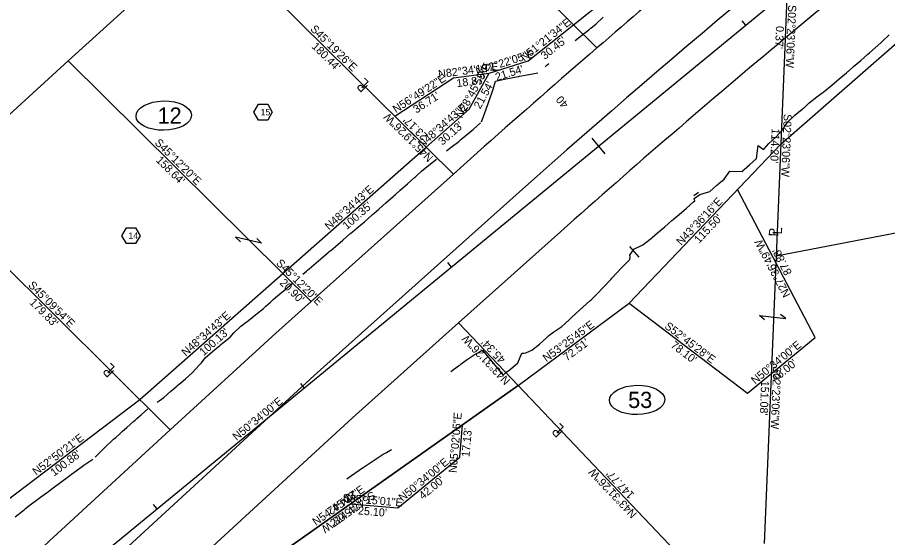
# Model space of a CAD drawing. Extents: x 1145508 to 2262867, y -3126236 to 2021677.
# Drawn here: x 1147204 to 1147660.6, y 2017213 to 2017486.3 of the extents above; entities that cross this region are included whole.
import ezdxf

# ---------------------------------------------------------------- set-up
doc = ezdxf.new("R2010")
doc.units = 0
for name, color, linetype in [('Default', 7, 'Continuous'), ('DSN_DRFT_Guideline-No-Plot', 7, 'Continuous'), ('DSN_RDWY_Alignment Annotation', 7, 'Continuous'), ('DSN_RDWY_Const Limits', 7, 'Continuous'), ('DSN_ROW_Annotation', 7, 'Continuous'), ('DSN_ROW_Esmnt', 7, 'Continuous'), ('DSN_ROW_Line', 7, 'Continuous'), ('DSN_ROW_Line-Annotation', 7, 'Continuous'), ('DSN_ROW_Prop-Line', 7, 'Continuous'), ('DSN_ROW_Prop-Line-Annotation', 7, 'Continuous'), ('E_Const Align', 7, 'Continuous'), ('EX_QSECTION', 7, 'Continuous'), ('EX_ROW', 7, 'Continuous'), ('EX_ROW_ANNOT', 7, 'Continuous'), ('EX_SIGN', 7, 'Continuous'), ('EX_SUBDIV_ANNOT', 7, 'Continuous')]:
    doc.layers.add(name, color=color, linetype=linetype)

msp = doc.modelspace()

# ---------------------------------------------------------------- linework, layer by layer
at = {"layer": 'Default'}
for p, q in [((1147468.99, 2017396.01), (1147359.68, 2017298.15)), ((1147359.68, 2017298.15), (1147243.01, 2017190.89))]:
    msp.add_line(p, q, dxfattribs=at)
msp.add_arc((1150521.47, 2013976.61), 4583.66, 127.59365, 131.75523, dxfattribs=at)
at = {"layer": 'DSN_DRFT_Guideline-No-Plot'}
msp.add_line((1147448.99, 2017418.38), (1147432.84, 2017403.92), dxfattribs=at)
msp.add_line((1147448.99, 2017418.38), (1147432.84, 2017403.92), dxfattribs=at)
msp.add_line((1147448.99, 2017418.38), (1147432.84, 2017403.92), dxfattribs=at)
at = {"layer": 'DSN_RDWY_Alignment Annotation'}
for p, q in [((1147584.16, 2017484.48), (1147586.06, 2017482.16)), ((1147505.44, 2017422.77), (1147512.18, 2017414.57)), ((1147429.69, 2017357.44), (1147431.59, 2017355.13)), ((1147352.45, 2017293.93), (1147354.36, 2017291.61)), ((1147275.21, 2017230.41), (1147277.12, 2017228.09))]:
    msp.add_line(p, q, dxfattribs=at)
at = {"layer": 'DSN_RDWY_Const Limits'}
for points in [[(1147496.71, 2017474.1), (1147499.91, 2017476.72), (1147503.82, 2017479.83), (1147504.53, 2017480.4), (1147504.86, 2017480.66), (1147507.73, 2017482.95), (1147511.41, 2017486.35)], [(1147431.44, 2017300.2), (1147435.5, 2017303.15), (1147436.06, 2017303.57), (1147436.9, 2017304.19), (1147439.51, 2017306.13), (1147443.66, 2017308.94), (1147443.67, 2017308.95), (1147448.08, 2017311.45), (1147458.78, 2017298.45), (1147459.37, 2017298.88), (1147460.12, 2017299.47), (1147462.73, 2017301.51), (1147466.58, 2017304.71), (1147468.77, 2017309.92), (1147469.66, 2017309.96), (1147470.86, 2017310.01), (1147473.95, 2017311.49), (1147477.88, 2017314.59), (1147481.56, 2017317.98), (1147482.08, 2017318.47), (1147482.77, 2017319.1), (1147485.55, 2017321), (1147489.69, 2017323.84), (1147493.34, 2017327.27), (1147493.86, 2017327.74), (1147494.55, 2017328.38), (1147497.03, 2017330.66), (1147500.71, 2017334.05), (1147504.4, 2017337.43), (1147505, 2017337.97), (1147505.51, 2017338.47), (1147507.98, 2017340.95), (1147511.53, 2017344.51), (1147514.98, 2017348.19), (1147515.52, 2017348.78), (1147516, 2017349.31), (1147518.39, 2017351.91), (1147521.12, 2017354.89), (1147521.81, 2017355.63), (1147525.41, 2017359.13), (1147525.56, 2017360.29), (1147525.45, 2017361.3), (1147527.51, 2017364.44), (1147532.11, 2017366.72), (1147536.05, 2017369.8), (1147536.7, 2017370.35), (1147537.12, 2017370.72), (1147539.85, 2017373.05), (1147543.65, 2017376.3), (1147547.45, 2017379.55), (1147548.09, 2017380.09), (1147548.53, 2017380.47), (1147551.26, 2017382.8), (1147555.06, 2017386.04), (1147558.81, 2017389.35), (1147559.5, 2017389.94), (1147559.07, 2017391.13), (1147562.04, 2017393.3), (1147567.32, 2017394.75), (1147571.07, 2017398.06), (1147571.75, 2017398.66), (1147572.07, 2017398.94), (1147574.83, 2017401.37), (1147577.87, 2017405.54), (1147584.45, 2017405.4), (1147585.09, 2017406.05), (1147585.38, 2017406.37), (1147588.08, 2017408.86), (1147591.78, 2017412.23), (1147592.73, 2017418.96), (1147595.55, 2017416.94), (1147595.82, 2017417.28), (1147598.34, 2017420.01), (1147602.05, 2017423.37), (1147605.4, 2017427.16), (1147605.97, 2017427.98), (1147606.14, 2017428.24), (1147608.36, 2017431.44), (1147611.91, 2017434.99), (1147615.87, 2017438.04), (1147616.7, 2017438.7), (1147616.77, 2017438.76), (1147619.52, 2017441.48), (1147623.43, 2017444.6), (1147627.49, 2017447.53), (1147628.34, 2017448.16), (1147628.42, 2017448.21), (1147631.44, 2017450.6), (1147635.19, 2017453.92), (1147638.99, 2017457.16), (1147639.8, 2017457.85), (1147639.87, 2017457.9), (1147642.8, 2017460.41), (1147646.54, 2017463.72), (1147650.35, 2017466.97), (1147651.15, 2017467.65), (1147651.22, 2017467.71), (1147654.15, 2017470.22), (1147657.11, 2017472.91), (1147657.85, 2017473.59), (1147661.49, 2017477.04)], [(1147480.98, 2017460.38), (1147481.61, 2017460.93), (1147482.04, 2017461.31), (1147482.8, 2017461.98)], [(1147447.52, 2017431.47), (1147447.8, 2017432.24), (1147449.19, 2017436.06), (1147450.76, 2017440.44), (1147451.15, 2017441.54), (1147453.11, 2017447.04), (1147453.44, 2017447.98), (1147453.66, 2017448.6), (1147454.86, 2017452.78), (1147460.34, 2017453.99), (1147465.9, 2017455.09), (1147466.86, 2017455.27), (1147467.48, 2017455.39), (1147471.5, 2017456.16), (1147477.09, 2017457.24)], [(1147429.22, 2017416.09), (1147431.65, 2017418.03), (1147435.59, 2017421.11), (1147436.18, 2017421.65), (1147436.72, 2017422.12), (1147439.42, 2017424.32), (1147443.29, 2017427.49), (1147447, 2017430.85)], [(1147353.83, 2017351.44), (1147355.65, 2017353), (1147356.21, 2017353.48), (1147357, 2017354.16), (1147359.45, 2017356.26), (1147363.24, 2017359.52), (1147367.07, 2017362.74), (1147367.61, 2017363.2), (1147368.42, 2017363.87), (1147370.89, 2017365.96), (1147374.68, 2017369.23), (1147378.46, 2017372.5), (1147379, 2017372.96), (1147379.79, 2017373.63), (1147382.28, 2017375.73), (1147386.09, 2017378.95), (1147386.09, 2017378.96), (1147389.83, 2017382.28), (1147389.84, 2017382.28), (1147390.39, 2017382.76), (1147391.11, 2017383.39), (1147393.6, 2017385.58), (1147397.35, 2017388.89), (1147401.1, 2017392.2), (1147401.64, 2017392.68), (1147402.35, 2017393.31), (1147404.86, 2017395.5), (1147408.62, 2017398.8), (1147412.36, 2017402.12), (1147412.9, 2017402.6), (1147413.59, 2017403.22), (1147416.1, 2017405.45), (1147419.91, 2017408.69), (1147423.83, 2017411.8)], [(1147277.32, 2017284.18), (1147278.34, 2017284.91), (1147280.75, 2017286.65), (1147284.51, 2017289.94), (1147287.58, 2017292.51), (1147288.34, 2017293.16), (1147288.92, 2017293.65), (1147289.88, 2017294.46), (1147292.21, 2017296.33), (1147295.89, 2017299.72), (1147299.27, 2017303.49), (1147299.81, 2017304.06), (1147300.64, 2017304.88), (1147302.56, 2017307.35), (1147306.28, 2017310.71), (1147310.16, 2017313.86), (1147310.75, 2017314.34), (1147311.65, 2017315.07), (1147314.04, 2017317.01), (1147315.54, 2017318.34), (1147317.57, 2017320.59), (1147321.25, 2017323.99), (1147321.94, 2017324.52), (1147322.64, 2017325.08), (1147325.18, 2017327.08), (1147329.11, 2017330.18), (1147333.02, 2017333.29), (1147333.54, 2017333.77), (1147334.41, 2017334.57), (1147336.72, 2017336.67), (1147338.22, 2017337.99), (1147340.51, 2017339.93), (1147344.32, 2017343.17), (1147344.84, 2017343.62), (1147345.74, 2017344.39), (1147348.12, 2017346.42)], [(1147244.69, 2017255.31), (1147246.67, 2017257.24), (1147250.27, 2017260.74), (1147253.93, 2017264.16), (1147254.45, 2017264.63), (1147255.58, 2017265.65), (1147257.64, 2017267.52), (1147259.13, 2017268.86), (1147261.35, 2017270.88), (1147265.13, 2017274.15), (1147265.73, 2017274.69), (1147266.66, 2017275.54), (1147268.84, 2017277.51), (1147272.34, 2017280.62)], [(1147376.83, 2017243.81), (1147379.22, 2017245.63), (1147383.38, 2017248.44), (1147384.1, 2017248.93), (1147384.84, 2017249.43), (1147387.54, 2017251.25), (1147391.71, 2017254.05), (1147395.96, 2017256.76), (1147396.58, 2017257.12), (1147397.62, 2017257.71), (1147400.31, 2017259.34)], [(1147202.85, 2017223.93), (1147206.77, 2017227.04), (1147207.7, 2017227.79), (1147208.24, 2017228.23), (1147210.71, 2017230.12), (1147214.72, 2017233.12), (1147218.73, 2017236.1), (1147218.74, 2017236.11), (1147219.52, 2017236.69), (1147220.4, 2017237.35), (1147222.74, 2017239.09), (1147222.75, 2017239.1), (1147226.75, 2017242.1), (1147230.76, 2017245.1), (1147231.52, 2017245.67), (1147232.41, 2017246.34), (1147234.76, 2017248.11), (1147238.87, 2017250.98), (1147242.99, 2017253.84), (1147243.59, 2017254.25)]]:
    msp.add_lwpolyline(points, dxfattribs=at)
at = {"layer": 'DSN_ROW_Esmnt'}
for p, q in [((1147432.75, 2017454.48), (1147451.46, 2017456.92)), ((1147432.75, 2017454.48), (1147451.46, 2017456.92)), ((1147402.03, 2017434.39), (1147432.75, 2017454.48)), ((1147402.03, 2017434.39), (1147432.75, 2017454.48)), ((1147421.07, 2017415.56), (1147402.03, 2017434.39)), ((1147418.5, 2017418.1), (1147402.03, 2017434.39)), ((1147432.84, 2017403.92), (1147432.84, 2017403.92)), ((1147622.64, 2017318.03), (1147581.91, 2017395.9)), ((1147524.94, 2017336.08), (1147587.11, 2017288.82)), ((1147587.11, 2017288.82), (1147622.64, 2017318.03)), ((1147436.06, 2017255.23), (1147437.57, 2017272.29)), ((1147403.62, 2017228.55), (1147436.06, 2017255.23)), ((1147378.61, 2017230.63), (1147403.62, 2017228.55))]:
    msp.add_line(p, q, dxfattribs=at)
at = {"layer": 'DSN_ROW_Line'}
for p, q in [((1147604.59, 2017419.72), (1147751.67, 2017548.43)), ((1147495.77, 2017482.46), (1147559.99, 2017533.8)), ((1147471.99, 2017463.44), (1147495.77, 2017482.46)), ((1147451.46, 2017456.92), (1147471.99, 2017463.44)), ((1147441.09, 2017438.03), (1147451.46, 2017456.92)), ((1147418.5, 2017418.1), (1147441.09, 2017438.03)), ((1147524.94, 2017336.08), (1147604.59, 2017419.72)), ((1147343.25, 2017351.71), (1147418.5, 2017418.1)), ((1147268.17, 2017285.46), (1147343.25, 2017351.71)), ((1147466.71, 2017292.88), (1147524.94, 2017336.08)), ((1147466.71, 2017292.88), (1147283.43, 2017163.37)), ((1147283.43, 2017163.37), (1147466.71, 2017292.88)), ((1147187.77, 2017224.53), (1147268.17, 2017285.46))]:
    msp.add_line(p, q, dxfattribs=at)
at = {"layer": 'DSN_ROW_Line-Annotation'}
for centre in [(1147280.76, 2017434.67), (1147529.2, 2017285.28)]:
    msp.add_ellipse(centre, major_axis=(14.54, 0.23), ratio=0.529773, dxfattribs=at)
at = {"layer": 'DSN_ROW_Prop-Line'}
for p, q in [((1147379.86, 2017596.84), (1147508.13, 2017470.27)), ((1147230.67, 2017463.48), (1147304.54, 2017530.78)), ((1147304.54, 2017530.78), (1147432.84, 2017403.92)), ((1147156.81, 2017396.18), (1147230.67, 2017463.48)), ((1147230.67, 2017463.48), (1147343.25, 2017351.71)), ((1148025.23, 2017442.03), (1147602.14, 2017360.88)), ((1147156.81, 2017396.18), (1147284.33, 2017269.39)), ((1147343.25, 2017351.71), (1147358.08, 2017336.99)), ((1147466.71, 2017292.88), (1147435.49, 2017325.75)), ((1147568.47, 2017185.74), (1147466.71, 2017292.88))]:
    msp.add_line(p, q, dxfattribs=at)
at = {"layer": 'DSN_ROW_Prop-Line-Annotation'}
for p, q in [((1147332.04, 2017367.63), (1147318.44, 2017370.79)), ((1147318.44, 2017370.79), (1147320.95, 2017368.28)), ((1147329.54, 2017370.13), (1147332.04, 2017367.63)), ((1147596.12, 2017327.42), (1147593.35, 2017329.63)), ((1147593.35, 2017329.63), (1147607.22, 2017328.02)), ((1147607.22, 2017328.02), (1147604.45, 2017330.23))]:
    msp.add_line(p, q, dxfattribs=at)
at = {"layer": 'E_Const Align'}
msp.add_line((1146840, 2016868.61), (1147825.51, 2017679.08), dxfattribs=at)
at = {"layer": 'EX_QSECTION'}
for p, q in [((1147610.26, 2017555.82), (1147606.91, 2017475.35)), ((1147606.9, 2017474.98), (1147602.14, 2017360.88)), ((1147606.91, 2017475.35), (1147606.9, 2017474.98)), ((1147602.14, 2017360.88), (1147595.86, 2017209.92))]:
    msp.add_line(p, q, dxfattribs=at)
at = {"layer": 'EX_ROW'}
for p, q in [((1147432.84, 2017403.92), (1147448.99, 2017418.38)), ((1147358.08, 2017336.99), (1147432.84, 2017403.92)), ((1147435.49, 2017325.75), (1147488.96, 2017373.63)), ((1147339.52, 2017320.37), (1147358.08, 2017336.99)), ((1147379.84, 2017275.93), (1147435.49, 2017325.75)), ((1147284.21, 2017269.51), (1147339.52, 2017320.37)), ((1147270.92, 2017175.79), (1147379.84, 2017275.93)), ((1147222.71, 2017212.97), (1147284.21, 2017269.51))]:
    msp.add_line(p, q, dxfattribs=at)
for centre, radius, start, end in [((1150521.47, 2013976.61), 4553.66, 127.59365, 129.79541), ((1150521.47, 2013976.61), 4613.66, 129.9481, 130.77845), ((1150521.47, 2013976.61), 4553.66, 129.79541, 131.75523), ((1150521.47, 2013976.61), 4613.66, 130.77845, 131.75549), ((1145304.01, 2019299.75), 2834.79, 312.2638, 312.59711)]:
    msp.add_arc(centre, radius, start, end, dxfattribs=at)
at = {"layer": 'EX_SIGN'}
for p, q in [((1147558.98, 2017392.72), (1147561.35, 2017394.53)), ((1147525.24, 2017365.86), (1147530.15, 2017360.31))]:
    msp.add_line(p, q, dxfattribs=at)
at = {"layer": 'EX_SUBDIV_ANNOT'}
for p, q in [((1147328.1, 2017436.5), (1147330.5, 2017440.66)), ((1147330.5, 2017440.66), (1147335.3, 2017440.66)), ((1147335.3, 2017440.66), (1147337.7, 2017436.5)), ((1147330.5, 2017432.34), (1147328.1, 2017436.5)), ((1147335.3, 2017432.34), (1147330.5, 2017432.34)), ((1147337.7, 2017436.5), (1147335.3, 2017432.34)), ((1147258.74, 2017371.58), (1147261.14, 2017375.74)), ((1147261.14, 2017375.74), (1147265.94, 2017375.74)), ((1147265.94, 2017375.74), (1147268.34, 2017371.58)), ((1147261.14, 2017367.42), (1147258.74, 2017371.58)), ((1147268.34, 2017371.58), (1147265.95, 2017367.42)), ((1147265.95, 2017367.42), (1147261.14, 2017367.42))]:
    msp.add_line(p, q, dxfattribs=at)

# ---------------------------------------------------------------- texts
at = {"layer": 'DSN_DRFT_Guideline-No-Plot'}
for rotation, p in [(357.0104, (1147495.72, 2017482.41)), (357.0104, (1147495.72, 2017482.41)), (357.0104, (1147495.72, 2017482.41)), (357.0104, (1147495.72, 2017482.41)), (357.0104, (1147495.73, 2017482.41)), (304.3313, (1147451.39, 2017456.93)), (304.3313, (1147451.39, 2017456.93)), (39.4333, (1147451.45, 2017456.85)), (39.4333, (1147451.45, 2017456.85)), (39.4333, (1147451.45, 2017456.85)), (39.4333, (1147451.45, 2017456.85)), (20.3026, (1147432.72, 2017454.41)), (20.3026, (1147432.72, 2017454.41)), (29.2871, (1147432.74, 2017454.42)), (178.3726, (1147418.54, 2017418.15)), (178.3726, (1147418.55, 2017418.15)), (178.3726, (1147418.55, 2017418.15)), (178.5801, (1147432.88, 2017403.97)), (178.5801, (1147432.89, 2017403.97)), (178.5801, (1147432.89, 2017403.97)), (178.5801, (1147432.89, 2017403.97)), (178.5801, (1147432.89, 2017403.97)), (352.0045, (1147581.87, 2017395.86)), (258.5235, (1147622.6, 2017318.08)), (181.0956, (1147587.15, 2017288.87))]:
    msp.add_text('+', height=0.1, rotation=rotation, dxfattribs=at).set_placement(p)
at = {"layer": 'DSN_RDWY_Alignment Annotation'}
for s, rotation, p in [('40', 129.4333, (1147493.41, 2017440.7)), ('N50°34\'00"E', 39.4333, (1147319.01, 2017263.71))]:
    msp.add_text(s, height=4.2, rotation=rotation, dxfattribs=at).set_placement(p)
at = {"layer": 'DSN_ROW_Annotation'}
for s, rotation, p in [('N51°21\'34"E', 38.6406, (1147469.99, 2017463)), ('S45°19\'26"E', 315.3238, (1147357.4, 2017479.78)), ("30.45'", 38.6406, (1147480.7, 2017463.88)), ("180.44'", 315.3238, (1147358.09, 2017470.66)), ('N72°22\'05"E', 17.6319, (1147445.2, 2017455.87)), ('N82°34\'19"E', 7.4279, (1147425.07, 2017454.38)), ('N28°45\'55"E', 61.2347, (1147437.28, 2017432.96)), ("21.54'", 17.6319, (1147455.5, 2017452.85)), ('N56°49\'22"E', 33.1772, (1147402.62, 2017435.85)), ("18.87'", 7.4279, (1147434.68, 2017449.59)), ("21.54'", 61.2347, (1147446.82, 2017437.87)), ("36.71'", 33.1772, (1147413.36, 2017435.7)), ('N48°34\'43"E', 41.4213, (1147416.41, 2017417.46)), ('N45°19\'26"W', 135.3238, (1147422.48, 2017412.9)), ("23.17'", 135.3238, (1147419.65, 2017424.14)), ("30.13'", 41.4213, (1147427.06, 2017418.85)), ('S45°12\'20"E', 315.2057, (1147275.7, 2017420.04)), ("158.64'", 315.2057, (1147276.37, 2017410.92)), ('N48°34\'43"E', 41.4213, (1147367.49, 2017374.3)), ('N43°36\'16"E', 46.3955, (1147552.35, 2017366.17)), ("100.35'", 41.4213, (1147376.86, 2017374.56)), ("115.50'", 46.3955, (1147561.66, 2017367.24)), ('N27°36\'49"W', 117.6136, (1147609.85, 2017340.54)), ("87.88'", 117.6136, (1147610.57, 2017352.11)), ('S45°12\'20"E', 315.2057, (1147339.4, 2017356.8)), ('S45°09\'54"E', 315.1649, (1147209.32, 2017345.24)), ("20.90'", 315.2057, (1147341.29, 2017346.47)), ("179.83'", 315.1649, (1147209.99, 2017336.12)), ('N48°34\'43"E', 41.4213, (1147292.32, 2017307.98)), ('N53°25\'45"E', 36.5709, (1147481.59, 2017305.04)), ("100.13'", 41.4213, (1147301.69, 2017308.24)), ('S52°45\'28"E', 322.7579, (1147543.23, 2017323.31)), ('N43°31\'26"W', 133.524, (1147462.88, 2017295.6)), ("45.34'", 133.524, (1147460.41, 2017306.92)), ("72.51'", 36.5709, (1147492.31, 2017305.53)), ("78.10'", 322.7579, (1147546.45, 2017313.32)), ('N50°34\'00"E', 39.4333, (1147591.13, 2017293.29)), ("46.00'", 39.4333, (1147601.82, 2017294.31)), ('N05°02\'05"E', 84.9652, (1147434.42, 2017246.85)), ('N52°50\'21"E', 37.1609, (1147213.83, 2017245.41)), ("17.13'", 84.9652, (1147441.18, 2017255.19)), ("100.88'", 37.1609, (1147223.19, 2017244.98)), ('N50°34\'00"E', 39.4333, (1147406.1, 2017231.75)), ("42.00'", 39.4333, (1147416.79, 2017232.77)), ('N43°31\'26"W', 133.524, (1147529.38, 2017225.59)), ("147.77'", 133.524, (1147528.07, 2017235.67)), ('N54°45\'08"E', 35.2478, (1147360.62, 2017219.02)), ('S54°45\'08"W', 215.2478, (1147390.1, 2017237.64)), ("224.42'", 215.2478, (1147380.18, 2017237.98)), ('S85°15\'01"E', 355.2502, (1147374.49, 2017231.87)), ("224.42'", 35.2478, (1147369.96, 2017218.27)), ("25.10'", 355.2502, (1147382.57, 2017225.18))]:
    msp.add_text(s, height=4.2, rotation=rotation, dxfattribs=at).set_placement(p)
at = {"layer": 'DSN_ROW_Line-Annotation'}
for s, p in [('12', (1147277.49, 2017430.46)), ('53', (1147524.47, 2017281.07))]:
    msp.add_text(s, height=8.5, dxfattribs=at).set_placement(p)
at = {"layer": 'DSN_ROW_Prop-Line-Annotation'}
for s, rotation, p in [('P', 135.169, (1147388.22, 2017449.99)), ('L', 135.169, (1147388.74, 2017452.17)), ('P', 88.1707, (1147603.26, 2017371.11)), ('L', 88.1707, (1147605.22, 2017372.21)), ('L', 135.169, (1147255.49, 2017302.38)), ('P', 135.169, (1147254.97, 2017300.2)), ('L', 135.1131, (1147491.16, 2017270.82)), ('P', 135.1131, (1147490.63, 2017268.64))]:
    msp.add_text(s, height=5, rotation=rotation, dxfattribs=at).set_placement(p)
at = {"layer": 'EX_ROW_ANNOT'}
for s, p in [('S02°23\'06"W', (1147608.54, 2017492.88)), ('S02°23\'06"W', (1147608.54, 2017492.88)), ("0.37'", (1147602.08, 2017481.82)), ("0.37'", (1147602.08, 2017481.82)), ('S02°23\'06"W', (1147606.16, 2017435.64)), ('S02°23\'06"W', (1147606.16, 2017435.64)), ("114.20'", (1147599.83, 2017427.99)), ("114.20'", (1147599.83, 2017427.99)), ('S02°23\'06"W', (1147600.64, 2017303.11)), ('S02°23\'06"W', (1147600.64, 2017303.11)), ("151.08'", (1147594.31, 2017295.46)), ("151.08'", (1147594.31, 2017295.46))]:
    msp.add_text(s, height=4.2, rotation=267.6149, dxfattribs=at).set_placement(p)
at = {"layer": 'EX_SUBDIV_ANNOT'}
for s, p in [('15', (1147331.6, 2017434.79)), ('14', (1147262.24, 2017369.87))]:
    msp.add_text(s, height=3.418, dxfattribs=at).set_placement(p)

doc.saveas('drawing.dxf')
